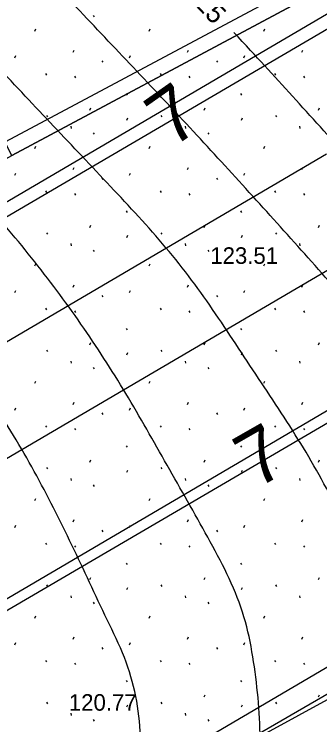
# Model space of a CAD drawing. Extents: x 412225 to 413380, y 4456471 to 4457189.
# Drawn here: x 413188.9 to 413211, y 4456858.5 to 4456910 of the extents above; entities that cross this region are included whole.
import ezdxf

# ---------------------------------------------------------------- set-up
doc = ezdxf.new("R2010")
doc.units = 0
for name, color, linetype in [('0_HALİHAZIR', 7, 'Continuous'), ('0_KADASTRO', 7, 'Continuous'), ('Level 28', 7, 'Continuous'), ('Level 41', 7, 'Continuous'), ('Level 54', 7, 'Continuous')]:
    doc.layers.add(name, color=color, linetype=linetype)

msp = doc.modelspace()

# ---------------------------------------------------------------- linework, layer by layer
at = {"layer": '0_HALİHAZIR'}
for points in [[(413308.103, 4456965.941), (413265.175, 4456940.384), (413047.239, 4456812.664), (412821.475, 4456681.363)], [(412841.576, 4456665.003), (413057.926, 4456790.466), (413273.464, 4456916.652), (413307.769, 4456936.91)], [(413101.589, 4456792.443), (413098.903, 4456797.22), (413080.986, 4456840.51), (413124.68, 4456865.219), (413175.605, 4456894.045), (413228.652, 4456922.382), (413248.055, 4456932.336), (413262.23, 4456891.913), (413262.792, 4456889.108), (413224.6, 4456867.435), (413186.768, 4456846.773), (413140.241, 4456816.307), (413141.746, 4456812.452)]]:
    msp.add_lwpolyline(points, dxfattribs=at)
for points in [[(413261.571, 4456886.638), (413261.004, 4456888.007), (413259.482, 4456890.566), (413257.716, 4456892.991), (413255.892, 4456895.372), (413254.026, 4456897.72), (413252.118, 4456900.035), (413250.173, 4456902.319), (413248.205, 4456904.582), (413246.209, 4456906.822), (413244.179, 4456909.03), (413242.115, 4456911.207), (413240.027, 4456913.362), (413237.932, 4456915.508), (413235.836, 4456917.655), (413233.741, 4456919.803), (413231.648, 4456921.952), (413229.556, 4456924.102), (413227.463, 4456926.251), (413225.353, 4456928.383), (413223.2, 4456930.471), (413220.998, 4456932.507), (413218.753, 4456934.497), (413216.485, 4456936.46), (413214.192, 4456938.395), (413211.871, 4456940.295), (413209.523, 4456942.162), (413207.153, 4456944.001), (413204.772, 4456945.826), (413204.514, 4456946.022)], [(413234.51, 4456907.826), (413232.483, 4456910.037), (413230.453, 4456912.245), (413228.418, 4456914.45), (413226.38, 4456916.652), (413224.337, 4456918.849), (413222.289, 4456921.04), (413220.233, 4456923.225), (413218.154, 4456925.388), (413216.037, 4456927.512), (413213.872, 4456929.588), (413211.667, 4456931.623), (413209.433, 4456933.624), (413207.168, 4456935.591), (413204.861, 4456937.508), (413202.508, 4456939.368), (413200.111, 4456941.17), (413197.685, 4456942.935), (413197.545, 4456943.035)], [(413246.707, 4456878.454), (413246.536, 4456879.066), (413245.323, 4456881.575), (413243.396, 4456883.871), (413241.538, 4456886.226), (413239.693, 4456888.592), (413237.877, 4456890.979), (413236.108, 4456893.402), (413234.378, 4456895.852), (413232.652, 4456898.305), (413230.882, 4456900.727), (413229.029, 4456903.084), (413227.095, 4456905.375), (413225.095, 4456907.61), (413223.064, 4456909.818), (413221.019, 4456912.014), (413218.968, 4456914.202), (413216.908, 4456916.383), (413214.838, 4456918.555), (413212.754, 4456920.713), (413210.647, 4456922.848), (413208.513, 4456924.956), (413206.351, 4456927.036), (413204.168, 4456929.093), (413201.965, 4456931.13), (413199.729, 4456933.129), (413197.42, 4456935.039), (413195.014, 4456936.821), (413192.532, 4456938.503), (413191.11, 4456939.425)], [(413221.76, 4456900.646), (413219.768, 4456902.888), (413217.763, 4456905.12), (413215.739, 4456907.335), (413213.696, 4456909.531), (413211.636, 4456911.712), (413209.56, 4456913.878), (413207.469, 4456916.029), (413205.359, 4456918.161), (413203.229, 4456920.274), (413201.081, 4456922.368), (413198.92, 4456924.449), (413196.749, 4456926.519), (413194.569, 4456928.581), (413192.332, 4456930.576), (413189.99, 4456932.422), (413187.533, 4456934.137), (413185.013, 4456935.766), (413184.585, 4456936.043)], [(413224.278, 4456824.774), (413224.586, 4456827.757), (413224.842, 4456830.745), (413225.032, 4456833.739), (413225.186, 4456836.735), (413225.319, 4456839.732), (413225.449, 4456842.729), (413225.589, 4456845.726), (413225.515, 4456848.709), (413225.197, 4456851.67), (413224.591, 4456854.607), (413223.938, 4456857.535), (413223.355, 4456860.476), (413223.012, 4456863.442), (413223.029, 4456866.412), (413223.303, 4456869.393), (413223.542, 4456872.373), (413223.139, 4456875.227), (413222.029, 4456877.864), (413220.305, 4456880.308), (413218.429, 4456882.648), (413216.528, 4456884.969), (413214.602, 4456887.269), (413212.649, 4456889.547), (413210.67, 4456891.801), (413208.672, 4456894.039), (413206.663, 4456896.267), (413204.648, 4456898.489), (413202.62, 4456900.7), (413200.577, 4456902.897), (413198.522, 4456905.082), (413196.46, 4456907.262), (413194.397, 4456909.439), (413192.326, 4456911.61), (413190.234, 4456913.759), (413188.105, 4456915.872), (413185.93, 4456917.938), (413183.713, 4456919.959), (413181.454, 4456921.931), (413179.137, 4456923.835), (413176.753, 4456925.652), (413174.301, 4456927.378), (413171.794, 4456929.025), (413170.314, 4456929.953)], [(413213.963, 4456822.444), (413214.138, 4456825.439), (413214.35, 4456828.431), (413214.609, 4456831.419), (413214.896, 4456834.406), (413215.187, 4456837.391), (413215.459, 4456840.379), (413215.702, 4456843.369), (413215.89, 4456846.363), (413215.986, 4456849.359), (413215.902, 4456852.351), (413215.603, 4456855.327), (413215.186, 4456858.297), (413214.839, 4456861.27), (413214.626, 4456864.259), (413214.366, 4456867.24), (413213.783, 4456870.145), (413212.802, 4456872.957), (413211.497, 4456875.651), (413210.02, 4456878.259), (413208.43, 4456880.801), (413206.783, 4456883.308), (413205.129, 4456885.811), (413203.46, 4456888.304), (413201.729, 4456890.751), (413199.866, 4456893.094), (413197.889, 4456895.347), (413195.843, 4456897.541), (413193.787, 4456899.725), (413191.726, 4456901.906), (413189.669, 4456904.089), (413187.62, 4456906.281), (413185.583, 4456908.483), (413183.552, 4456910.691), (413181.494, 4456912.873), (413179.382, 4456915.002), (413177.204, 4456917.063), (413174.929, 4456919.013), (413172.517, 4456920.773), (413169.965, 4456922.335), (413167.313, 4456923.735), (413164.625, 4456925.066), (413162.694, 4456925.984)], [(413202.109, 4456818.426), (413202.386, 4456818.766), (413203.599, 4456821.315), (413204.112, 4456824.25), (413204.425, 4456827.233), (413204.725, 4456830.217), (413205.053, 4456833.199), (413205.356, 4456836.184), (413205.645, 4456839.17), (413205.928, 4456842.156), (413206.204, 4456845.144), (413206.462, 4456848.133), (413206.68, 4456851.124), (413206.802, 4456854.12), (413206.727, 4456857.108), (413206.569, 4456860.1), (413206.221, 4456863.075), (413205.623, 4456865.969), (413204.605, 4456868.762), (413203.261, 4456871.437), (413201.804, 4456874.06), (413200.324, 4456876.669), (413198.846, 4456879.28), (413197.344, 4456881.876), (413195.78, 4456884.435), (413194.136, 4456886.942), (413192.403, 4456889.39), (413190.59, 4456891.778), (413188.703, 4456894.109), (413186.75, 4456896.386), (413184.752, 4456898.623), (413182.737, 4456900.845), (413180.736, 4456903.08), (413178.763, 4456905.34), (413176.812, 4456907.619), (413174.861, 4456909.897), (413172.839, 4456912.11), (413170.651, 4456914.137), (413168.297, 4456915.978), (413165.827, 4456917.681), (413163.344, 4456919.364), (413160.859, 4456921.046), (413158.374, 4456922.726), (413157.593, 4456923.254)], [(413195.36, 4456833.825), (413195.707, 4456836.805), (413196.053, 4456839.785), (413196.398, 4456842.765), (413196.749, 4456845.745), (413197.103, 4456848.724), (413197.452, 4456851.703), (413197.788, 4456854.684), (413197.997, 4456857.673), (413197.681, 4456860.563), (413196.858, 4456863.38), (413195.607, 4456866.106), (413194.335, 4456868.823), (413193.05, 4456871.534), (413191.723, 4456874.224), (413190.325, 4456876.877), (413188.829, 4456879.475), (413187.224, 4456882.006), (413185.524, 4456884.477), (413183.758, 4456886.901), (413181.952, 4456889.296), (413180.116, 4456891.669), (413178.262, 4456894.028), (413176.4, 4456896.38), (413174.536, 4456898.73), (413172.67, 4456901.08), (413170.798, 4456903.424), (413168.91, 4456905.755), (413166.986, 4456908.056), (413164.927, 4456910.224), (413162.718, 4456912.235), (413160.362, 4456914.09), (413157.949, 4456915.872), (413155.499, 4456917.602), (413153.007, 4456919.271), (413150.481, 4456920.899)], [(413230.993, 4456869.408), (413230.97, 4456871.006), (413230.625, 4456873.974), (413229.898, 4456876.843), (413228.713, 4456879.563), (413227.165, 4456882.119), (413225.433, 4456884.566), (413223.625, 4456886.96), (413221.79, 4456889.333), (413219.924, 4456891.682), (413218.017, 4456893.997), (413216.061, 4456896.271), (413214.071, 4456898.515), (413212.061, 4456900.743), (413210.048, 4456902.967), (413208.028, 4456905.185), (413206, 4456907.396), (413204.79, 4456908.706)]]:
    msp.add_spline(points, degree=3, dxfattribs=at)
at = {"layer": '0_KADASTRO'}
msp.add_lwpolyline([(413172.785, 4456930.957), (413176.183, 4456932.617), (413179.633, 4456934.325), (413184.212, 4456936.591), (413194.161, 4456941.515), (413203.945, 4456946.299), (413211.116, 4456949.841), (413212.288, 4456950.42), (413227.203, 4456920.401), (413188.699, 4456899.781), (413174.23, 4456928.127)], close=True, dxfattribs=at)
msp.add_lwpolyline([(413101.802, 4456789.154), (413081.926, 4456838.759), (413084.666, 4456842.03), (413188.699, 4456899.781), (413227.203, 4456920.401), (413243.637, 4456929.202), (413244.91, 4456926.572), (413267.668, 4456885.105), (413263.645, 4456882.832), (413242.448, 4456870.545), (413228.112, 4456862.238), (413213.766, 4456853.922), (413193.383, 4456842.116), (413184.691, 4456837.083), (413183.689, 4456836.502), (413165.406, 4456825.906)], dxfattribs=at)
at = {"layer": 'Level 28'}
msp.add_lwpolyline([(413262.177, 4456890.065), (413193.882, 4456850.478)], dxfattribs=at)
at = {"layer": 'Level 41'}
for p, q in [((413194.6, 4456909.938), (413194.67, 4456909.831)), ((413202.893, 4456909.938), (413202.963, 4456909.831)), ((413190.363, 4456908.794), (413190.435, 4456908.954)), ((413198.656, 4456908.794), (413198.728, 4456908.954)), ((413206.949, 4456908.794), (413207.021, 4456908.954)), ((413193.135, 4456907.264), (413193.205, 4456907.424)), ((413201.428, 4456907.264), (413201.498, 4456907.424)), ((413209.721, 4456907.264), (413209.791, 4456907.424)), ((413188.925, 4456906.856), (413188.996, 4456907.016)), ((413195.23, 4456906.648), (413195.301, 4456906.542)), ((413197.218, 4456906.856), (413197.289, 4456907.016)), ((413203.523, 4456906.648), (413203.594, 4456906.542)), ((413205.511, 4456906.856), (413205.582, 4456907.016)), ((413191.145, 4456905.719), (413191.216, 4456905.612)), ((413199.438, 4456905.719), (413199.509, 4456905.612)), ((413207.731, 4456905.719), (413207.802, 4456905.612)), ((413193.244, 4456905.527), (413193.315, 4456905.42)), ((413201.537, 4456905.527), (413201.608, 4456905.42)), ((413209.83, 4456905.527), (413209.901, 4456905.42)), ((413196.982, 4456904.266), (413197.053, 4456904.159)), ((413205.275, 4456904.266), (413205.346, 4456904.159)), ((413194.341, 4456903.073), (413194.412, 4456903.232)), ((413202.634, 4456903.073), (413202.705, 4456903.232)), ((413210.927, 4456903.073), (413210.998, 4456903.232)), ((413191.212, 4456902.689), (413191.283, 4456902.582)), ((413197.04, 4456902.344), (413197.112, 4456902.504)), ((413199.505, 4456902.689), (413199.576, 4456902.582)), ((413205.333, 4456902.344), (413205.405, 4456902.504)), ((413207.798, 4456902.689), (413207.869, 4456902.582)), ((413192.97, 4456901.898), (413192.988, 4456901.738)), ((413201.263, 4456901.898), (413201.281, 4456901.738)), ((413209.556, 4456901.898), (413209.574, 4456901.738)), ((413194.6, 4456901.428), (413194.67, 4456901.321)), ((413202.893, 4456901.428), (413202.963, 4456901.321)), ((413190.363, 4456900.284), (413190.435, 4456900.444)), ((413198.656, 4456900.284), (413198.728, 4456900.444)), ((413206.949, 4456900.284), (413207.021, 4456900.444)), ((413193.135, 4456898.754), (413193.205, 4456898.914)), ((413201.428, 4456898.754), (413201.498, 4456898.914)), ((413209.721, 4456898.754), (413209.791, 4456898.914)), ((413188.925, 4456898.346), (413188.996, 4456898.506)), ((413197.218, 4456898.346), (413197.289, 4456898.506)), ((413205.511, 4456898.346), (413205.582, 4456898.506)), ((413195.23, 4456898.138), (413195.301, 4456898.032)), ((413203.523, 4456898.138), (413203.594, 4456898.032)), ((413191.145, 4456897.209), (413191.216, 4456897.102)), ((413193.244, 4456897.017), (413193.315, 4456896.91)), ((413199.438, 4456897.209), (413199.509, 4456897.102)), ((413201.537, 4456897.017), (413201.608, 4456896.91)), ((413207.731, 4456897.209), (413207.802, 4456897.102)), ((413209.83, 4456897.017), (413209.901, 4456896.91)), ((413196.982, 4456895.756), (413197.053, 4456895.649)), ((413205.275, 4456895.756), (413205.346, 4456895.649)), ((413194.341, 4456894.563), (413194.412, 4456894.722)), ((413202.634, 4456894.563), (413202.705, 4456894.722)), ((413210.927, 4456894.563), (413210.998, 4456894.722)), ((413191.212, 4456894.179), (413191.283, 4456894.072)), ((413197.04, 4456893.834), (413197.112, 4456893.994)), ((413199.505, 4456894.179), (413199.576, 4456894.072)), ((413205.333, 4456893.834), (413205.405, 4456893.994)), ((413207.798, 4456894.179), (413207.869, 4456894.072)), ((413192.97, 4456893.388), (413192.988, 4456893.228)), ((413201.263, 4456893.388), (413201.281, 4456893.228)), ((413209.556, 4456893.388), (413209.574, 4456893.228)), ((413194.6, 4456892.918), (413194.67, 4456892.811)), ((413202.893, 4456892.918), (413202.963, 4456892.811)), ((413190.363, 4456891.774), (413190.435, 4456891.934)), ((413198.656, 4456891.774), (413198.728, 4456891.934)), ((413206.949, 4456891.774), (413207.021, 4456891.934)), ((413193.135, 4456890.244), (413193.205, 4456890.404)), ((413201.428, 4456890.244), (413201.498, 4456890.404)), ((413209.721, 4456890.244), (413209.791, 4456890.404)), ((413188.925, 4456889.836), (413188.996, 4456889.996)), ((413195.23, 4456889.628), (413195.301, 4456889.522)), ((413197.218, 4456889.836), (413197.289, 4456889.996)), ((413203.523, 4456889.628), (413203.594, 4456889.522)), ((413205.511, 4456889.836), (413205.582, 4456889.996)), ((413191.145, 4456888.699), (413191.216, 4456888.592)), ((413199.438, 4456888.699), (413199.509, 4456888.592)), ((413207.731, 4456888.699), (413207.802, 4456888.592)), ((413193.244, 4456888.507), (413193.315, 4456888.4)), ((413201.537, 4456888.507), (413201.608, 4456888.4)), ((413209.83, 4456888.507), (413209.901, 4456888.4)), ((413196.982, 4456887.246), (413197.053, 4456887.139)), ((413205.275, 4456887.246), (413205.346, 4456887.139)), ((413194.341, 4456886.053), (413194.412, 4456886.212)), ((413202.634, 4456886.053), (413202.705, 4456886.212)), ((413210.927, 4456886.053), (413210.998, 4456886.212)), ((413191.212, 4456885.669), (413191.283, 4456885.562)), ((413197.04, 4456885.324), (413197.112, 4456885.484)), ((413199.505, 4456885.669), (413199.576, 4456885.562)), ((413205.333, 4456885.324), (413205.405, 4456885.484)), ((413207.798, 4456885.669), (413207.869, 4456885.562)), ((413192.97, 4456884.878), (413192.988, 4456884.718)), ((413201.263, 4456884.878), (413201.281, 4456884.718)), ((413209.556, 4456884.878), (413209.574, 4456884.718)), ((413194.6, 4456884.408), (413194.67, 4456884.301)), ((413202.893, 4456884.408), (413202.963, 4456884.301)), ((413190.363, 4456883.264), (413190.435, 4456883.424)), ((413198.656, 4456883.264), (413198.728, 4456883.424)), ((413206.949, 4456883.264), (413207.021, 4456883.424)), ((413193.135, 4456881.734), (413193.205, 4456881.894)), ((413201.428, 4456881.734), (413201.498, 4456881.894)), ((413209.721, 4456881.734), (413209.791, 4456881.894)), ((413188.925, 4456881.326), (413188.996, 4456881.486)), ((413197.218, 4456881.326), (413197.289, 4456881.486)), ((413205.511, 4456881.326), (413205.582, 4456881.486)), ((413195.23, 4456881.118), (413195.301, 4456881.012)), ((413203.523, 4456881.118), (413203.594, 4456881.012)), ((413191.145, 4456880.189), (413191.216, 4456880.082)), ((413193.244, 4456879.997), (413193.315, 4456879.89)), ((413199.438, 4456880.189), (413199.509, 4456880.082)), ((413201.537, 4456879.997), (413201.608, 4456879.89)), ((413207.731, 4456880.189), (413207.802, 4456880.082)), ((413209.83, 4456879.997), (413209.901, 4456879.89)), ((413196.982, 4456878.736), (413197.053, 4456878.629)), ((413205.275, 4456878.736), (413205.346, 4456878.629)), ((413194.341, 4456877.543), (413194.412, 4456877.702)), ((413202.634, 4456877.543), (413202.705, 4456877.702)), ((413210.927, 4456877.543), (413210.998, 4456877.702)), ((413191.212, 4456877.159), (413191.283, 4456877.052)), ((413197.04, 4456876.814), (413197.112, 4456876.974)), ((413199.505, 4456877.159), (413199.576, 4456877.052)), ((413205.333, 4456876.814), (413205.405, 4456876.974)), ((413207.798, 4456877.159), (413207.869, 4456877.052)), ((413192.97, 4456876.368), (413192.988, 4456876.208)), ((413201.263, 4456876.368), (413201.281, 4456876.208)), ((413209.556, 4456876.368), (413209.574, 4456876.208)), ((413194.6, 4456875.898), (413194.67, 4456875.791)), ((413202.893, 4456875.898), (413202.963, 4456875.791)), ((413190.363, 4456874.754), (413190.435, 4456874.914)), ((413198.656, 4456874.754), (413198.728, 4456874.914)), ((413206.949, 4456874.754), (413207.021, 4456874.914)), ((413193.135, 4456873.224), (413193.205, 4456873.384)), ((413201.428, 4456873.224), (413201.498, 4456873.384)), ((413209.721, 4456873.224), (413209.791, 4456873.384)), ((413188.925, 4456872.816), (413188.996, 4456872.976)), ((413195.23, 4456872.608), (413195.301, 4456872.502)), ((413197.218, 4456872.816), (413197.289, 4456872.976)), ((413203.523, 4456872.608), (413203.594, 4456872.502)), ((413205.511, 4456872.816), (413205.582, 4456872.976)), ((413191.145, 4456871.679), (413191.216, 4456871.572)), ((413199.438, 4456871.679), (413199.509, 4456871.572)), ((413207.731, 4456871.679), (413207.802, 4456871.572)), ((413193.244, 4456871.487), (413193.315, 4456871.38)), ((413201.537, 4456871.487), (413201.608, 4456871.38)), ((413209.83, 4456871.487), (413209.901, 4456871.38)), ((413196.982, 4456870.226), (413197.053, 4456870.119)), ((413205.275, 4456870.226), (413205.346, 4456870.119)), ((413194.341, 4456869.033), (413194.412, 4456869.192)), ((413202.634, 4456869.033), (413202.705, 4456869.192)), ((413210.927, 4456869.033), (413210.998, 4456869.192)), ((413191.212, 4456868.649), (413191.283, 4456868.542)), ((413199.505, 4456868.649), (413199.576, 4456868.542)), ((413207.798, 4456868.649), (413207.869, 4456868.542)), ((413197.04, 4456868.304), (413197.112, 4456868.464)), ((413205.333, 4456868.304), (413205.405, 4456868.464)), ((413192.97, 4456867.858), (413192.988, 4456867.698)), ((413201.263, 4456867.858), (413201.281, 4456867.698)), ((413209.556, 4456867.858), (413209.574, 4456867.698)), ((413194.6, 4456867.388), (413194.67, 4456867.281)), ((413202.893, 4456867.388), (413202.963, 4456867.281)), ((413190.363, 4456866.244), (413190.435, 4456866.404)), ((413198.656, 4456866.244), (413198.728, 4456866.404)), ((413206.949, 4456866.244), (413207.021, 4456866.404)), ((413193.135, 4456864.714), (413193.205, 4456864.874)), ((413201.428, 4456864.714), (413201.498, 4456864.874)), ((413209.721, 4456864.714), (413209.791, 4456864.874)), ((413188.925, 4456864.306), (413188.996, 4456864.466)), ((413197.218, 4456864.306), (413197.289, 4456864.466)), ((413205.511, 4456864.306), (413205.582, 4456864.466)), ((413195.23, 4456864.098), (413195.301, 4456863.992)), ((413203.523, 4456864.098), (413203.594, 4456863.992)), ((413191.145, 4456863.169), (413191.216, 4456863.062)), ((413193.244, 4456862.977), (413193.315, 4456862.87)), ((413199.438, 4456863.169), (413199.509, 4456863.062)), ((413201.537, 4456862.977), (413201.608, 4456862.87)), ((413207.731, 4456863.169), (413207.802, 4456863.062)), ((413209.83, 4456862.977), (413209.901, 4456862.87)), ((413196.982, 4456861.716), (413197.053, 4456861.609)), ((413205.275, 4456861.716), (413205.346, 4456861.609)), ((413194.341, 4456860.523), (413194.412, 4456860.682)), ((413202.634, 4456860.523), (413202.705, 4456860.682)), ((413210.927, 4456860.523), (413210.998, 4456860.682)), ((413191.212, 4456860.139), (413191.283, 4456860.032)), ((413197.04, 4456859.794), (413197.112, 4456859.954)), ((413199.505, 4456860.139), (413199.576, 4456860.032)), ((413205.333, 4456859.794), (413205.405, 4456859.954)), ((413207.798, 4456860.139), (413207.869, 4456860.032)), ((413192.97, 4456859.348), (413192.988, 4456859.188)), ((413201.263, 4456859.348), (413201.281, 4456859.188)), ((413194.6, 4456858.878), (413194.67, 4456858.771)), ((413202.893, 4456858.878), (413202.963, 4456858.771))]:
    msp.add_line(p, q, dxfattribs=at)
at = {"layer": 'Level 54'}
for points in [[(413046.364, 4456813.097), (413264.689, 4456941.261), (413308.102, 4456966.436)], [(413307.773, 4456937.825), (413273.289, 4456917.582), (413057.204, 4456790.554)], [(413211.499, 4456899.877), (413102.863, 4456836.014)], [(413108.887, 4456831.188), (413218.485, 4456895.526)], [(413227.751, 4456872.193), (413119.132, 4456808.34)]]:
    msp.add_lwpolyline(points, dxfattribs=at)

# ---------------------------------------------------------------- texts
at = {"layer": '0_HALİHAZIR'}
msp.add_text('125', height=1.4, rotation=313.0679, dxfattribs=at).set_placement((413201.193, 4456911.487))
for s, p in [('123.51 ', (413203.082, 4456891.923)), ('120.77 ', (413192.833, 4456859.524))]:
    msp.add_text(s, height=1.2, dxfattribs=at).set_placement(p)
at = {"layer": 'Level 54'}
for rotation, p in [(35.0814, (413200.288, 4456900.26)), (29.7926, (413206.398, 4456875.567))]:
    msp.add_text('7', height=4, rotation=rotation, dxfattribs=at).set_placement(p)

doc.saveas('drawing.dxf')
